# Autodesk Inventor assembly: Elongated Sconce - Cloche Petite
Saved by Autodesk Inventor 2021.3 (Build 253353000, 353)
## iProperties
Created: 2022-08
Part Number: Elongated Sconce - Cloche Petite
Document SubType Name: Assembly
Designer: Administrator
Title: Elongated Sconce - Cloche Petite v6
Author: Administrator
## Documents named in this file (11)
- c:\worker\convert-fusion-r04\tmp\job-1\97\output\files\f98770a9-93e4-4195-b1e6-5744bc38e7eb\5c075078-5443-4a3a-87ac-012b7432b12c.iam
- c:\worker\convert-fusion-r04\tmp\job-1\97\output\files\f98770a9-93e4-4195-b1e6-5744bc38e7eb\Back Plate.ipt
- c:\worker\convert-fusion-r04\tmp\job-1\97\output\files\f98770a9-93e4-4195-b1e6-5744bc38e7eb\Knurled Shade Ring.ipt
- c:\worker\convert-fusion-r04\tmp\job-1\97\output\files\f98770a9-93e4-4195-b1e6-5744bc38e7eb\Screw Top.ipt
- c:\worker\convert-fusion-r04\tmp\job-1\97\output\files\f98770a9-93e4-4195-b1e6-5744bc38e7eb\Sconce.ipt
- c:\worker\convert-fusion-r04\tmp\job-1\97\output\files\f98770a9-93e4-4195-b1e6-5744bc38e7eb\Socket Cover.ipt
- c:\worker\convert-fusion-r04\tmp\job-1\97\output\files\f98770a9-93e4-4195-b1e6-5744bc38e7eb\Screw Bottom.ipt
- c:\worker\convert-fusion-r04\tmp\job-1\97\output\files\f98770a9-93e4-4195-b1e6-5744bc38e7eb\Socket - E26.ipt
- c:\worker\convert-fusion-r04\tmp\job-1\97\output\files\f98770a9-93e4-4195-b1e6-5744bc38e7eb\T9-Bulb.ipt
- c:\worker\convert-fusion-r04\tmp\job-1\97\output\files\f98770a9-93e4-4195-b1e6-5744bc38e7eb\E26 Base.ipt
- c:\worker\convert-fusion-r04\tmp\job-1\97\output\files\f98770a9-93e4-4195-b1e6-5744bc38e7eb\Part20.ipt
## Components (10 placed, 10 different names)
1. Back Plate:1
2. Knurled Shade Ring:1
3. Screw Top:1
4. Sconce:1
5. Socket Cover:1
6. Screw Bottom:1
7. Socket - E26:1
8. T9-Bulb:1
9. E26 Base:1
10. Part20
